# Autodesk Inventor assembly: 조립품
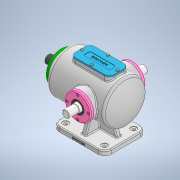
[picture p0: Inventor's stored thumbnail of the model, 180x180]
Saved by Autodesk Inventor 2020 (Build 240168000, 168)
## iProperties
Created: 2021-11
Part Number: 조립품
Document SubType Name: Assembly
Designer: USER
Author: USER
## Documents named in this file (14)
- C:\Users\USER\Desktop\711106V1009\조립품.iam
- C:\Users\USER\Desktop\711106V1009\본체.ipt
- C:\Users\USER\Desktop\711106V1009\베어링 6205.ipt
- 베어링 6205.ipt
- C:\Users\USER\Desktop\711106V1009\볼트 M4x0.7.ipt
- C:\Users\USER\Desktop\711106V1009\부시.ipt
- C:\Users\USER\Desktop\711106V1009\상부커버.ipt
- C:\Users\USER\Desktop\711106V1009\슬라이드 커버.ipt
- C:\Users\USER\Desktop\711106V1009\슬라이드.ipt
- C:\Users\USER\Desktop\711106V1009\오일실.ipt
- 오일실.ipt
- C:\Users\USER\Desktop\711106V1009\육각머리볼트 M4.ipt
- C:\Users\USER\Desktop\711106V1009\축 커버.ipt
- C:\Users\USER\Desktop\711106V1009\편심축.ipt
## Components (12 placed, 1 different names)
1. M4x0.7:2
2. M4x0.7:4
3. M4x0.7:5
4. M4x0.7:6
5. M4x0.7:3
6. M4x0.7:7
7. M4x0.7:8
8. M4x0.7:9
9. M4x0.7:1
10. M4x0.7:10
11. M4x0.7:11
12. M4x0.7:12
